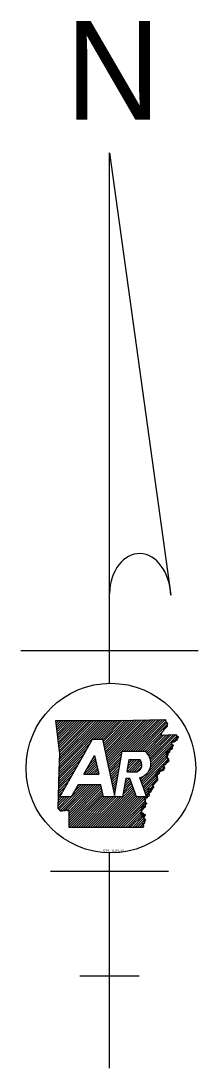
# Model space of a CAD drawing. Extents: x -42408 to 34530, y -43140 to 20491.
# Drawn here: x -3560 to -3296, y -6 to 1550 of the extents above; entities that cross this region are included whole.
import ezdxf

# ---------------------------------------------------------------- set-up
doc = ezdxf.new("R2010")
doc.units = 0
doc.layers.add('30', color=7, linetype='Continuous')

msp = doc.modelspace()

# ---------------------------------------------------------------- linework, layer by layer
at = {"layer": '30'}
for p, q in [((-3427.9, 1353.7), (-3337, 696.6)), ((-3427.9, 565.7), (-3427.9, 1353.7)), ((-3559.5, 614.4), (-3296.4, 614.4)), ((-3507.8, 509.3), (-3506.7, 510.4)), ((-3507.4, 506.2), (-3503.2, 510.4)), ((-3507, 503.1), (-3499.7, 510.4)), ((-3506.6, 500), (-3496.2, 510.4)), ((-3506.2, 496.9), (-3492.8, 510.3)), ((-3505.8, 493.8), (-3489.3, 510.3)), ((-3505.4, 490.7), (-3485.8, 510.3)), ((-3505.1, 487.6), (-3482.3, 510.3)), ((-3504.7, 484.5), (-3478.8, 510.3)), ((-3504.3, 481.4), (-3475.3, 510.3)), ((-3503.9, 478.3), (-3471.9, 510.3)), ((-3503.5, 475.2), (-3468.4, 510.3)), ((-3503.1, 472.1), (-3464.9, 510.3)), ((-3502.7, 469), (-3461.4, 510.3)), ((-3502.6, 434.3), (-3426.5, 510.4)), ((-3502.5, 437.9), (-3430, 510.4)), ((-3502.4, 441.5), (-3433.5, 510.4)), ((-3502.4, 465.9), (-3457.9, 510.3)), ((-3502.3, 445.1), (-3437, 510.4)), ((-3502.2, 448.7), (-3440.5, 510.4)), ((-3502, 452.3), (-3444, 510.4)), ((-3502, 462.8), (-3454.5, 510.3)), ((-3501.9, 455.9), (-3447.5, 510.4)), ((-3501.8, 459.5), (-3451, 510.3)), ((-3450.9, 482.5), (-3423, 510.4)), ((-3447.4, 482.5), (-3419.5, 510.4)), ((-3443.9, 482.5), (-3416, 510.4)), ((-3440.5, 482.5), (-3412.5, 510.5)), ((-3438.3, 481.2), (-3409, 510.6)), ((-3437.7, 478.4), (-3405.4, 510.6)), ((-3437.1, 475.5), (-3401.9, 510.7)), ((-3436.5, 472.6), (-3398.3, 510.7)), ((-3435.8, 469.7), (-3394.8, 510.8)), ((-3435.2, 466.9), (-3391.3, 510.8)), ((-3434.6, 464), (-3387.7, 510.9)), ((-3434, 461.1), (-3384.2, 510.9)), ((-3433.4, 458.3), (-3380.7, 511)), ((-3432.8, 455.4), (-3377.1, 511)), ((-3432.2, 452.5), (-3373.6, 511.1)), ((-3431.5, 449.7), (-3370, 511.2)), ((-3430.9, 446.8), (-3366.5, 511.2)), ((-3430.3, 443.9), (-3362.9, 511.3)), ((-3406.1, 464.6), (-3359.4, 511.4)), ((-3402.6, 464.6), (-3355.8, 511.5)), ((-3399.2, 464.6), (-3352.2, 511.6)), ((-3395.7, 464.6), (-3348.7, 511.6)), ((-3392.2, 464.6), (-3345.1, 511.7)), ((-3388.7, 464.6), (-3344.3, 509)), ((-3385.2, 464.6), (-3342.6, 507.2)), ((-3381.7, 464.6), (-3342.2, 504.2)), ((-3501.6, 396.7), (-3453, 482.5)), ((-3453, 482.5), (-3438.6, 482.5)), ((-3378.3, 464.6), (-3350.1, 492.7)), ((-3375.1, 464.3), (-3350.8, 488.6)), ((-3373.2, 462.7), (-3347.2, 488.8)), ((-3371.5, 461), (-3343.5, 489)), ((-3370, 459), (-3339.8, 489.1)), ((-3368.7, 456.8), (-3336.1, 489.3)), ((-3367.6, 454.4), (-3332.5, 489.5)), ((-3366.8, 451.7), (-3329.2, 489.3)), ((-3366.4, 448.7), (-3327.5, 487.5)), ((-3329.1, 482.5), (-3325.9, 485.6)), ((-3502.9, 427.1), (-3460.3, 469.7)), ((-3502.8, 430.7), (-3455.8, 477.7)), ((-3367.1, 441), (-3335.4, 472.6)), ((-3366.3, 445.2), (-3335.9, 475.7)), ((-3339.4, 465.2), (-3335, 469.5)), ((-3503.1, 419.9), (-3469.4, 453.6)), ((-3503, 423.5), (-3464.8, 461.6)), ((-3465.9, 430.4), (-3450, 458.5)), ((-3457, 446.1), (-3449, 454)), ((-3452.4, 454.1), (-3449.6, 456.9)), ((-3429.7, 441.1), (-3409.9, 460.8)), ((-3429.1, 438.2), (-3410.7, 456.6)), ((-3428.5, 435.3), (-3411.4, 452.4)), ((-3409.3, 464.6), (-3375.5, 464.6)), ((-3401.9, 434.2), (-3383.6, 452.5)), ((-3401.2, 438.4), (-3387.1, 452.5)), ((-3400.5, 442.6), (-3390.6, 452.5)), ((-3399.7, 446.8), (-3394.1, 452.5)), ((-3399, 451.1), (-3397.5, 452.5)), ((-3398.8, 452.5), (-3382.9, 452.5)), ((-3381.4, 419.7), (-3342.8, 458.3)), ((-3380.5, 417.1), (-3342.2, 455.4)), ((-3379.6, 414.6), (-3341.5, 452.6)), ((-3370.1, 434.5), (-3343.5, 461.1)), ((-3503.3, 412.7), (-3478.5, 437.5)), ((-3503.2, 416.3), (-3473.9, 445.6)), ((-3465.7, 430.4), (-3447.8, 448.3)), ((-3462.2, 430.4), (-3447.2, 445.4)), ((-3461.5, 438.1), (-3448.4, 451.2)), ((-3458.7, 430.4), (-3446.6, 442.6)), ((-3455.2, 430.4), (-3445.9, 439.7)), ((-3451.8, 430.4), (-3445.3, 436.8)), ((-3427.9, 432.5), (-3412.1, 448.2)), ((-3427.2, 429.6), (-3412.9, 443.9)), ((-3426.6, 426.7), (-3413.6, 439.7)), ((-3398.4, 434.2), (-3381.7, 451)), ((-3395, 434.2), (-3380.5, 448.7)), ((-3391.5, 434.2), (-3379.8, 445.8)), ((-3388, 434.2), (-3380.1, 442.1)), ((-3378.6, 412), (-3340.9, 449.8)), ((-3352.8, 434.4), (-3347.9, 439.3)), ((-3503.6, 405.5), (-3487.6, 421.5)), ((-3503.5, 409.1), (-3483, 429.5)), ((-3465.9, 430.4), (-3444, 430.4)), ((-3448.3, 430.4), (-3444.7, 434)), ((-3444.8, 430.4), (-3444.1, 431.1)), ((-3426, 423.8), (-3414.3, 435.5)), ((-3425.4, 421), (-3415.1, 431.3)), ((-3424.8, 418.1), (-3415.8, 427.1)), ((-3424.2, 415.2), (-3416.5, 422.9)), ((-3405.7, 412.8), (-3397, 421.6)), ((-3404.9, 417.1), (-3398, 424)), ((-3404.2, 421.3), (-3401.5, 424)), ((-3397.9, 424), (-3403.7, 424)), ((-3401.9, 434.2), (-3387.5, 434.2)), ((-3387.8, 396.7), (-3397.9, 424)), ((-3383.6, 425.5), (-3373, 396.7)), ((-3383.3, 424.7), (-3382.3, 425.8)), ((-3382.4, 422.2), (-3375.8, 428.8)), ((-3377.7, 409.5), (-3356.8, 430.4)), ((-3376.7, 406.9), (-3357.2, 426.5)), ((-3375.8, 404.4), (-3357.6, 422.6)), ((-3503.8, 398.3), (-3496.7, 405.4)), ((-3503.7, 401.9), (-3492.1, 413.5)), ((-3503.1, 378.1), (-3466.5, 414.7)), ((-3501, 376.7), (-3463, 414.7)), ((-3498.5, 375.7), (-3459.5, 414.7)), ((-3494.4, 376.4), (-3456, 414.7)), ((-3490.8, 376.4), (-3452.5, 414.7)), ((-3488.1, 375.7), (-3449.1, 414.7)), ((-3488, 368.9), (-3442.1, 414.7)), ((-3488, 372.3), (-3445.6, 414.7)), ((-3488, 365.4), (-3440.3, 413.1)), ((-3488, 361.9), (-3439.6, 410.2)), ((-3487.9, 358.4), (-3439, 407.4)), ((-3474.7, 414.7), (-3484.9, 396.7)), ((-3481, 403.7), (-3469.9, 414.7)), ((-3476.4, 411.7), (-3473.4, 414.7)), ((-3440.6, 414.7), (-3474.7, 414.7)), ((-3453.1, 351.5), (-3393.2, 411.4)), ((-3449.6, 351.5), (-3392.3, 408.8)), ((-3446.2, 351.5), (-3391.3, 406.3)), ((-3423.6, 412.4), (-3417.3, 418.6)), ((-3422.9, 409.5), (-3418, 414.4)), ((-3422.3, 406.6), (-3418.8, 410.2)), ((-3421.7, 403.8), (-3419.5, 406)), ((-3407.9, 400.2), (-3394.1, 413.9)), ((-3407.1, 404.4), (-3395.1, 416.5)), ((-3406.4, 408.6), (-3396, 419)), ((-3374.9, 401.9), (-3364.2, 412.5)), ((-3373.9, 399.3), (-3365.7, 407.6)), ((-3504.4, 380.3), (-3488, 396.7)), ((-3504.3, 383.9), (-3491.4, 396.7)), ((-3504.2, 387.5), (-3494.9, 396.7)), ((-3504.1, 391.1), (-3498.4, 396.7)), ((-3503.9, 394.7), (-3501.2, 397.4)), ((-3484.9, 396.7), (-3501.6, 396.7)), ((-3487.9, 355), (-3438.4, 404.5)), ((-3487.9, 351.5), (-3437.8, 401.6)), ((-3484.4, 351.5), (-3437.2, 398.7)), ((-3480.9, 351.5), (-3435.7, 396.7)), ((-3477.4, 351.5), (-3432.2, 396.7)), ((-3474, 351.5), (-3428.7, 396.7)), ((-3470.5, 351.5), (-3425.3, 396.7)), ((-3467, 351.5), (-3421.8, 396.7)), ((-3463.5, 351.5), (-3418.3, 396.7)), ((-3460.1, 351.5), (-3414.8, 396.7)), ((-3456.6, 351.5), (-3411.3, 396.7)), ((-3442.7, 351.5), (-3390.4, 403.7)), ((-3439.2, 351.5), (-3389.4, 401.2)), ((-3408.5, 396.7), (-3436.8, 396.7)), ((-3435.7, 351.4), (-3388.5, 398.7)), ((-3432.2, 351.4), (-3386.9, 396.7)), ((-3428.8, 351.4), (-3383.5, 396.7)), ((-3425.3, 351.4), (-3380, 396.7)), ((-3421.8, 351.4), (-3376.5, 396.7)), ((-3421.1, 400.9), (-3420.2, 401.8)), ((-3418.3, 351.4), (-3375.3, 394.4)), ((-3414.9, 351.4), (-3375.2, 391.1)), ((-3373, 396.7), (-3387.8, 396.7)), ((-3411.4, 351.4), (-3375, 387.8)), ((-3407.9, 351.4), (-3374.9, 384.4)), ((-3404.4, 351.4), (-3380.6, 375.2)), ((-3400.9, 351.4), (-3379.5, 372.8)), ((-3397.5, 351.4), (-3378.4, 370.4)), ((-3394, 351.4), (-3377.4, 368)), ((-3390.5, 351.4), (-3376.3, 365.6)), ((-3387, 351.4), (-3375.4, 363)), ((-3383.6, 351.4), (-3377, 358)), ((-3380.1, 351.4), (-3378.5, 352.9)), ((-3427.9, -6.1), (-3427.9, 313.7)), ((-3515.7, 286.5), (-3340.2, 286.5)), ((-3471.8, 130.7), (-3384.1, 130.7))]:
    msp.add_line(p, q, dxfattribs=at)
for points in [[(-3507.9, 510.3), (-3459.9, 510.3), (-3417.7, 510.4), (-3367.9, 511.2), (-3344.9, 511.7)], [(-3507.9, 510.4), (-3459.8, 510.3), (-3417.7, 510.4), (-3367.9, 511.2), (-3344.9, 511.7)], [(-3504.4, 380.4), (-3501.7, 461), (-3507.9, 510.4)], [(-3502.6, 435.7), (-3501.8, 461), (-3507.9, 510.3)], [(-3438.6, 482.5), (-3420.7, 399), (-3409.3, 464.6)], [(-3329.8, 489.6), (-3325.6, 485.3), (-3336, 476.8), (-3334.9, 468.2), (-3343.8, 462.3), (-3340.7, 449.1), (-3347.6, 442.8), (-3348.2, 436), (-3356.5, 433), (-3357.8, 420.2), (-3363.8, 413.8), (-3366.7, 404.1), (-3375.4, 396.2), (-3374.8, 382.1), (-3380.7, 375.4), (-3375.3, 363.4), (-3379, 351.4)], [(-3352, 488.5), (-3329.5, 489.7)], [(-3352, 488.5), (-3329.5, 489.7)], [(-3450, 458.5), (-3444, 430.4)], [(-3401.9, 434.2), (-3398.8, 452.5)], [(-3504.4, 380.3), (-3502.6, 435.7)], [(-3403.7, 424), (-3408.5, 396.7)], [(-3436.8, 396.7), (-3440.6, 414.7)], [(-3379, 351.3), (-3487.9, 351.5), (-3488, 375.6)], [(-3379, 351.4), (-3487.9, 351.5), (-3488, 375.6)]]:
    msp.add_lwpolyline(points, dxfattribs=at)
for centre, major_axis, ratio, start_param, end_param in [((-3382.5, 695.2), (-1.9, 63.2), 0.719778, 4.712385, 7.768526), ((-3390.9, 444.8), (-11.1, 0), 0.999987, 1.887169, 3.90762), ((-3388.1, 446.8), (-21.8, 0), 0.999987, 1.777838, 4.099264)]:
    msp.add_ellipse(centre, major_axis=major_axis, ratio=ratio, start_param=start_param, end_param=end_param, dxfattribs=at)
msp.add_ellipse((-3425.9, 439.7), major_axis=(126, 0), ratio=0.999976, dxfattribs=at)
for points in [[(-3344.9, 511.7), (-3344.7, 510.4), (-3344.3, 509.7), (-3344.3, 508.5), (-3343.7, 507.9), (-3342.9, 507.4), (-3342.1, 506.6), (-3341.9, 505.6), (-3342.2, 504.5), (-3342.2, 503.3), (-3342.3, 502.3), (-3342.5, 501.4), (-3343.2, 500.7), (-3343.9, 500.1), (-3344.5, 499.5), (-3345, 498.9), (-3345.8, 498.2), (-3346.5, 497.4), (-3347.2, 496.8), (-3347.8, 495.9), (-3348.1, 495), (-3348.8, 494.3), (-3349.3, 493.7), (-3350, 492.9), (-3350.4, 492.2), (-3351, 491.2), (-3351.2, 490.3), (-3351.6, 489.6), (-3351.7, 489.5)], [(-3344.9, 511.7), (-3344.7, 510.4), (-3344.3, 509.7), (-3344.3, 508.5), (-3343.7, 508), (-3342.9, 507.4), (-3342.1, 506.6), (-3341.9, 505.5), (-3342.2, 504.5), (-3342.2, 503.3), (-3342.4, 502.3), (-3342.5, 501.4), (-3343.2, 500.7), (-3343.9, 500.1), (-3344.6, 499.5), (-3345, 498.9), (-3345.8, 498.1), (-3346.5, 497.4), (-3347.2, 496.7), (-3347.8, 495.9), (-3348.1, 495), (-3348.8, 494.3), (-3349.3, 493.7), (-3350, 492.9), (-3350.4, 492.1), (-3351.1, 491.2), (-3351.2, 490.3), (-3351.7, 489.6), (-3351.7, 489.5)], [(-3329.8, 489.7), (-3329.5, 489.7), (-3328.5, 488.6), (-3328, 487.7), (-3327.3, 487.2), (-3326.6, 487), (-3326, 486.3), (-3325.7, 485.5), (-3325.9, 484.9), (-3326.7, 484.8), (-3327.6, 484.7), (-3328.5, 484.7), (-3329.2, 484.1), (-3328.6, 483.3), (-3327.7, 482.5), (-3327.5, 481.7), (-3327.9, 481), (-3328.9, 480.6), (-3329.8, 480.2), (-3330.6, 479.5), (-3331, 478.8), (-3332, 478.5), (-3332.9, 478.2), (-3333.7, 478.1), (-3334.7, 478), (-3335.6, 477.5), (-3336, 476.7), (-3335.9, 475.7), (-3335.9, 474.5), (-3334.9, 474.1), (-3334.1, 474.1), (-3333.2, 473.6), (-3333.3, 473), (-3333.9, 472.1), (-3334.7, 471.5), (-3335.4, 471.2), (-3336.1, 470.5), (-3335.9, 469.9), (-3335.3, 469.5), (-3334.8, 468.8), (-3334.9, 468.2), (-3335.6, 467.8), (-3336.4, 467.9), (-3336.9, 468.7), (-3337.6, 468.9), (-3338.1, 469.2), (-3338.8, 468.8), (-3338.8, 467.9), (-3339, 467), (-3338.8, 466.3), (-3338.6, 465.4), (-3338.6, 464.7), (-3338.8, 463.6), (-3339.3, 462.6), (-3339.9, 462.3), (-3340.2, 463.4), (-3340.3, 464.3), (-3340.6, 464.9), (-3341.1, 464.9), (-3341.7, 464.5), (-3342.4, 463.8), (-3343.3, 463), (-3343.8, 462.3), (-3343.5, 461.4), (-3342.9, 461.1), (-3342.3, 461.3), (-3342.1, 461.9), (-3341.6, 462), (-3341.1, 461.1)], [(-3341.1, 461.1), (-3341, 460.2), (-3341.5, 459.3), (-3341.7, 458.4), (-3341.6, 457.4), (-3342.5, 456.9), (-3343.4, 456.3), (-3342.9, 455.6), (-3342, 455), (-3341.1, 454.5), (-3340.6, 454), (-3340.4, 452.8), (-3340.2, 452), (-3339.9, 450.9), (-3339.8, 450.2), (-3340.4, 449.3), (-3341, 449.1), (-3341.7, 449.3), (-3342.4, 449.3), (-3343, 448.8), (-3343.5, 447.9), (-3343.9, 447.1), (-3344.3, 446.4), (-3344.6, 445.6), (-3345.2, 444.7), (-3346, 444.6), (-3347, 444.3), (-3347.6, 443.7), (-3347.5, 442.6), (-3346.9, 441.8), (-3346.5, 440.9), (-3346.2, 440.1), (-3346.4, 439.1), (-3346.8, 438.4), (-3347.3, 437.9), (-3347.6, 437), (-3347.9, 436.2), (-3348.3, 436), (-3349, 436.1), (-3349.8, 436.2), (-3350.4, 436.2), (-3351, 435.8), (-3351.7, 436), (-3352.3, 436.8), (-3352.9, 437.3), (-3353.5, 437.5), (-3354.1, 437.2), (-3354.2, 436.2), (-3353.9, 435.2), (-3353.6, 433.8), (-3353.9, 433), (-3354, 431.6)], [(-3354, 431.6), (-3355, 430.8), (-3355.5, 430), (-3358.2, 430.2), (-3358.1, 429.3), (-3359, 428.8), (-3359.9, 428.2), (-3359.4, 427.5), (-3358.5, 426.8), (-3357.6, 426.3), (-3357, 425.8), (-3356.9, 424.6), (-3356.7, 423.8), (-3356.4, 422.8), (-3356.3, 422), (-3356.9, 421.2), (-3357.5, 421), (-3358.1, 421.2), (-3358.9, 421.2), (-3359.5, 420.7), (-3360, 419.8), (-3360.4, 419), (-3360.7, 418.3), (-3361.1, 417.5), (-3361.7, 416.6), (-3362.5, 416.5), (-3363.5, 416.2), (-3364, 415.6), (-3363.9, 414.5), (-3363.4, 413.7), (-3363, 412.8), (-3362.7, 412), (-3362.8, 411), (-3363.3, 410.2), (-3363.8, 409.8), (-3364, 408.8), (-3364.4, 408.1), (-3364.8, 407.9), (-3365.5, 408), (-3366.3, 408.1), (-3366.9, 408), (-3367.5, 407.7), (-3368.2, 407.9), (-3368.8, 408.6), (-3369.4, 409.2), (-3370, 409.4), (-3370.6, 409.1), (-3370.7, 408.1), (-3370.4, 407.1), (-3370.1, 405.7), (-3370.4, 404.9), (-3370.5, 403.5)], [(-3374.5, 392.3), (-3374.8, 391.6), (-3375.1, 390.4), (-3375, 389.4), (-3374.6, 388.6), (-3373.9, 388.1), (-3373.1, 387.4), (-3373.1, 386.4), (-3373.6, 386), (-3374.6, 386.2), (-3375.4, 386.6), (-3376.1, 386.4), (-3377, 386), (-3377.7, 385.8), (-3377.7, 384.4), (-3376.8, 383.4), (-3376, 383.4), (-3375, 383.3), (-3374.7, 382.2), (-3375.3, 381.3), (-3376.1, 380.9), (-3377.3, 381.4), (-3378.1, 382), (-3378.9, 382.5), (-3379.9, 382.8), (-3380.5, 382.7), (-3380.7, 381.4), (-3380.2, 380.3), (-3379.5, 379.5), (-3378.8, 378.5), (-3378.9, 377.8), (-3379.4, 377.6), (-3380.4, 377.3), (-3380.9, 377.1), (-3381.1, 376.8), (-3380.8, 375.8), (-3380.5, 374.7), (-3380.5, 373.9), (-3380.8, 373.1), (-3381.3, 371.9), (-3381.3, 371.2), (-3380.9, 370.8), (-3380.5, 370.9), (-3379.9, 371.3), (-3379.5, 371.8), (-3379.2, 372.4), (-3378.6, 372.9), (-3377.8, 372.5), (-3377.6, 371.5), (-3378, 370.7), (-3378.7, 370.4), (-3379.4, 370.1), (-3380, 369.4), (-3379.9, 368.6), (-3379.4, 368.2), (-3378.3, 368.4), (-3377.6, 368.8), (-3377.1, 369.2), (-3376.6, 369.7), (-3376.4, 370.2), (-3376, 370.7), (-3375.3, 370.9), (-3375, 370.4), (-3375.1, 369.4), (-3375.5, 368.5), (-3376.1, 367.7), (-3376.7, 367.1), (-3377.5, 365.9), (-3377.3, 364.8), (-3377, 363.8), (-3376.6, 363.1), (-3375.9, 363.3), (-3375.1, 363.4), (-3374.6, 363), (-3374.7, 362.1), (-3375.3, 361.3), (-3375.8, 360.6), (-3376.1, 359.5), (-3376, 358.7), (-3376, 358.1), (-3376.3, 357.3), (-3376.7, 356.9), (-3377.8, 356.9), (-3378.9, 357), (-3379.6, 356.7), (-3379.4, 355.7), (-3378.8, 354.9), (-3378.3, 354.6), (-3377.6, 353.7), (-3377.3, 353), (-3377.4, 352.5), (-3377.8, 351.9), (-3379, 351.3)], [(-3374.5, 392.3), (-3374.8, 391.6), (-3375.1, 390.4), (-3375, 389.4), (-3374.6, 388.6), (-3373.9, 388.1), (-3373.1, 387.4), (-3373.1, 386.4), (-3373.6, 386), (-3374.6, 386.2), (-3375.4, 386.6), (-3376.1, 386.4), (-3377, 386), (-3377.7, 385.8), (-3377.7, 384.4), (-3376.8, 383.4), (-3376, 383.4), (-3375, 383.3), (-3374.7, 382.2), (-3375.3, 381.3), (-3376.1, 380.9), (-3377.3, 381.4), (-3378.1, 382), (-3378.9, 382.5), (-3379.9, 382.8), (-3380.5, 382.7), (-3380.7, 381.4), (-3380.2, 380.3), (-3379.5, 379.5), (-3378.8, 378.5), (-3378.9, 377.8), (-3379.4, 377.6), (-3380.4, 377.3), (-3380.9, 377.1), (-3381.1, 376.8), (-3380.8, 375.8), (-3380.5, 374.7), (-3380.5, 373.9), (-3380.8, 373.1), (-3381.3, 371.9), (-3381.3, 371.2), (-3380.9, 370.8), (-3380.5, 370.9), (-3379.9, 371.3), (-3379.5, 371.8), (-3379.2, 372.4), (-3378.6, 372.9), (-3377.8, 372.5), (-3377.6, 371.5), (-3378, 370.7), (-3378.7, 370.4), (-3379.4, 370.1), (-3380, 369.4), (-3379.9, 368.6), (-3379.4, 368.2), (-3378.3, 368.4), (-3377.6, 368.8), (-3377.1, 369.2), (-3376.6, 369.7), (-3376.4, 370.2), (-3376, 370.7), (-3375.3, 370.9), (-3375, 370.4), (-3375.1, 369.4), (-3375.5, 368.5), (-3376.1, 367.7), (-3376.7, 367.1), (-3377.5, 365.9), (-3377.3, 364.8), (-3377, 363.8), (-3376.6, 363.1), (-3375.9, 363.3), (-3375.1, 363.4), (-3374.6, 363), (-3374.7, 362.1), (-3375.3, 361.3), (-3375.8, 360.6), (-3376.1, 359.5), (-3376, 358.7), (-3376, 358.1), (-3376.3, 357.3), (-3376.7, 356.9), (-3377.8, 356.9), (-3378.9, 357), (-3379.6, 356.7), (-3379.4, 355.7), (-3378.8, 354.9), (-3378.3, 354.6), (-3377.6, 353.7), (-3377.3, 353), (-3377.4, 352.5), (-3377.8, 351.9), (-3379, 351.3)], [(-3370.5, 403.5), (-3370.6, 403.4), (-3371.1, 402.8), (-3370.8, 401.7), (-3369.6, 401.3), (-3369.1, 400.3), (-3369.1, 399.4), (-3369.4, 398.2), (-3370, 397.6), (-3371, 397.4), (-3371.8, 397.2), (-3371.9, 395.9), (-3372.3, 395.2), (-3372.9, 395), (-3373.8, 395.4), (-3374.4, 395.7), (-3375, 395.9), (-3375.8, 396.4), (-3376.5, 396.3), (-3376.3, 395), (-3376.2, 395), (-3375.5, 394), (-3374.8, 393.2), (-3374.5, 392.3)], [(-3370.5, 403.5), (-3370.6, 403.4), (-3371.1, 402.8), (-3370.8, 401.7), (-3369.6, 401.3), (-3369.1, 400.3), (-3369.1, 399.4), (-3369.4, 398.2), (-3370, 397.6), (-3371, 397.4), (-3371.8, 397.2), (-3371.9, 395.9), (-3372.3, 395.2), (-3372.9, 395), (-3373.8, 395.4), (-3374.4, 395.7), (-3375, 395.9), (-3375.8, 396.4), (-3376.5, 396.3), (-3376.3, 395), (-3376.2, 395), (-3375.5, 394), (-3374.8, 393.2), (-3374.5, 392.3)], [(-3488, 375.6), (-3487.9, 375.5), (-3488.4, 375.9), (-3489.2, 376.3), (-3490.1, 376.3), (-3491.2, 376.5), (-3492.1, 376.6), (-3493, 377.2), (-3494.1, 376.6), (-3495.2, 376.1), (-3495.8, 376.6), (-3496.7, 376.3), (-3497.3, 376.4), (-3498.3, 375.7), (-3499.3, 376), (-3500, 375.8), (-3500.9, 375.8), (-3501.1, 376.8), (-3502, 377), (-3502.7, 377.4), (-3503.2, 378.4), (-3503.6, 379.2), (-3504.4, 380.4)], [(-3488, 375.6), (-3487.9, 375.5), (-3488.4, 375.9), (-3489.2, 376.3), (-3490.1, 376.3), (-3491.2, 376.5), (-3492.1, 376.6), (-3493, 377.2), (-3494, 376.6), (-3495.2, 376.1), (-3495.8, 376.6), (-3496.7, 376.2), (-3497.3, 376.4), (-3498.3, 375.7), (-3499.3, 376), (-3500, 375.8), (-3500.9, 375.8), (-3501.1, 376.8), (-3502, 377), (-3502.7, 377.4), (-3503.2, 378.4), (-3503.6, 379.2), (-3504.4, 380.3)]]:
    msp.add_spline(points, degree=3, dxfattribs=at)

# ---------------------------------------------------------------- texts
for s, height, p in [('N', 146.7, (-3493.3, 1403.2)), ('STS 10-03-17', 3.644, (-3437.9, 314.7))]:
    msp.add_text(s, height=height, dxfattribs=at).set_placement(p)

doc.saveas('drawing.dxf')
